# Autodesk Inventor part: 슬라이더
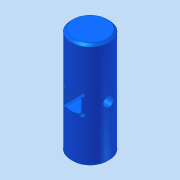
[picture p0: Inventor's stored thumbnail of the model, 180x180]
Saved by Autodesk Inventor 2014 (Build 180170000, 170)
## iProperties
Company: 한국ATC센터
Created: 2015-04
Part Number: 슬라이더
Document SubType Name: Modeling
Designer: KYOUNG IL JANG
Density: 1 g/cm^3
Material: 일반
Mass: 11.2119 g
Surface Area: 38.9014 cm^2
Volume: 11.2119 cm^3
Appearance: 청록색
Author: KYOUNG IL JANG
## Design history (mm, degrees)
sketch "스케치1"
  geometry: C1 r 9 at (0, 0); 1 further point
  constraints: 1 centre point, 1 coincident
  dimensions: "d0" = 18 diameter of C1
extrude "돌출1" new body sketch "스케치1" stored distance "d1" = 50; taper "d2" = 0 deg
node "작업 평면1"
sketch "스케치3"
  geometry: L1 (4, 25)-(-4, 25); L2 (-4, 25)-(-4, -25); L3 (-4, -25)-(4, -25); L4 (4, -25)-(4, 25); 3 further points
  constraints: 8 end point, 2 midpoint, 2 parallel, 1 horizontal, 1 horizontal alignment, 1 perpendicular, 1 vertical alignment
  dimensions: "d5" = 8 distance of L1.start L1.end; "d6" = 50 distance of L1.end L2.end
extrude "돌출3" cut sketch "스케치3" stored distance "d7" = 8; taper "d8" = 0 deg
sketch "스케치4"
  geometry: 5 further points
hole "구멍1" sketch "스케치4" at (4, 4), (-4, 4), (-4, -4), (4, -4) diameter "d9" = 2; stored, may be unused: countersink angle "d13" = 90 deg, drill point angle "d15" = 118 deg; dims "d10" = 6, "d11" = 4, "d12" = 2, "d14" = 8
node "작업 평면2"
sketch "스케치5"
  geometry: 1 further point
hole "구멍2" sketch "스케치5" at (0, 0) diameter "d16" = 5; stored, may be unused: countersink angle "d20" = 90 deg, drill point angle "d22" = 118 deg; dims "d17" = 6, "d18" = 4, "d19" = 2, "d21" = 8
chamfer "모따기1" distance "d23" = 1; stored, may be unused: second distance "d24" = 2, angle "d25" = 45 deg
node "솔리드1"
mirror "대칭1"
